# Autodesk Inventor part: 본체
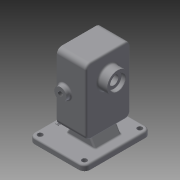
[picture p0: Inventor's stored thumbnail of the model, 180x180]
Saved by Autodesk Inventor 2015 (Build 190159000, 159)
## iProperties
Created: 2020-04
Part Number: 본체
Material: 일반
Document SubType Name: Modeling
Designer: CAD-08
Density: 1 g/cm^3
Appearance: 기본값
Author: CAD-08
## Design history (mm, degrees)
sketch "스케치1"
  geometry: L1 (50, -60)-(-50, -60); L2 (-50, -60)-(-50, 60); L3 (-50, 60)-(50, 60); L4 (50, 60)-(50, -60); L5 (50, -60)-(-50, 60); L6 (-50, -60)-(50, 60); 1 further point
  constraints: 12 end point, 2 midpoint, 2 parallel, 1 horizontal, 1 perpendicular
  dimensions: "d0" = 100 distance of L2.end L3.end; "d1" = 120 distance of L1.end L2.end
extrude "돌출1" new body sketch "스케치1" distance "d2" = 10; taper "d3" = 0 deg
fillet "모깎기1" dims "d4" = 10
sketch "스케치2"
  geometry: A1 r 10 centre (-40, 50) between (-40, 60) and (-50, 50) reference; A2 r 10 centre (-40, -50) between (-50, -50) and (-40, -60) reference; A3 r 10 centre (40, -50) between (40, -60) and (50, -50) reference; A4 r 10 centre (40, 50) between (50, 50) and (40, 60) reference; 1 further point
hole "구멍1" sketch "스케치2" at (-40, -50), (-40, 50), (40, -50), (40, 50) diameter "d5" = 9; stored, may be unused: countersink angle "d9" = 90 deg, drill point angle "d11" = 118 deg; dims "d6" = 6, "d7" = 4, "d8" = 2, "d10" = 8
sketch "스케치3"
  geometry: L1 (50, -50)-(50, 50) reference; L2 (-20, 24)-(33, 24); L3 (33, 24)-(33, -24); L4 (33, -24)-(-20, -24); L5 (-20, -24)-(-20, 24); L6 (0, 0)-(-20, 0)
  constraints: 10 end point, 2 horizontal, 2 parallel, 1 midpoint, 1 perpendicular, 1 other
  dimensions: "d12" = 48 distance of L4.end L2.start; "d13" = 53 distance of L3.end L4.end; "d14" = 17 distance between parallel lines of L1 L3
extrude "돌출2" join sketch "스케치3" distance "d15" = 50; taper "d16" = 0 deg
feature "면 기울기1" dims angle "d17" = 30 deg
feature "면 기울기2" dims angle "d18" = 30 deg
sketch "스케치5"
  geometry: L1 (-33, 10)-(-6.5, 55.899) reference; L2 (-6.5, 55.899)-(20, 10) reference; L3 (20, 10)-(50, 10) reference; L4 (50, 10)-(50, 0) reference; L5 (50, 0)-(-50, 0) reference; L6 (-50, 0)-(-50, 10) reference; L7 (-50, 10)-(-33, 10) reference; L8 (20, 30)-(-33, 30); L9 (-33, 30)-(-33, 150); L10 (-33, 150)-(20, 150); L11 (20, 150)-(20, 30); L12 (-6.5, 55.899)-(-6.5, 30); 1 further point
  constraints: 10 end point, 2 parallel, 1 horizontal, 1 midpoint, 1 perpendicular, 1 vertical, 1 other
  dimensions: "d26" = 120 distance of L10.end L8.start; "d27" = 53 distance of L9.end L10.end; "d28" = 150 distance between parallel lines of L5 L10
extrude "돌출4" join sketch "스케치5" stored distance "d29" = 80; taper "d30" = 0 deg
fillet "모깎기2" dims "d31" = 9
sketch "스케치7"
  geometry: A1 r 9 centre (9, 62) between (9, 71) and (0, 62) reference; A2 r 9 centre (9, 0) between (0, 0) and (9, -9) reference; A3 r 9 centre (111, 0) between (111, -9) and (120, 0) reference; A4 r 9 centre (111, 62) between (120, 62) and (111, 71) reference; 1 further point
hole "구멍2" sketch "스케치7" at (111, 62), (111, 0), (9, 62), (9, 0) diameter "d37" = 4.134; stored, may be unused: countersink angle "d41" = 90 deg, drill point angle "d43" = 118 deg; dims "d38" = 10, "d39" = 4, "d40" = 2, "d42" = 12
sketch "스케치8"
  geometry: C1 r 2.067 at (111, 62) reference; 2 further points
  constraints: 1 horizontal alignment
  dimensions: "d44" = 29 distance of C1.centre point (82, 62)
hole "구멍3" sketch "스케치8" at (82, 62) diameter "d45" = 4.134; stored, may be unused: countersink angle "d49" = 90 deg, drill point angle "d51" = 118 deg; dims "d46" = 10, "d47" = 4, "d48" = 2, "d50" = 12
sketch "스케치9"
  geometry: C1 r 2.067 at (9, 62) reference; 2 further points
  constraints: 1 horizontal alignment
  dimensions: "d52" = 29 distance of C1.centre point (38, 62)
hole "구멍4" sketch "스케치9" at (38, 62) diameter "d53" = 4.134; stored, may be unused: countersink angle "d57" = 90 deg, drill point angle "d59" = 118 deg; dims "d54" = 10, "d55" = 4, "d56" = 2, "d58" = 12
sketch "스케치12"
  geometry: L1 (9, 71)-(111, 71) reference; L2 (14, 31)-(106, 31); L3 (38, 7)-(82, 7); L4 (82, 55)-(38, 55); L5 (-30, -19)-(-30, 81) reference; A1 r 24 centre (38, 31) between (38, 55) and (38, 7); A2 r 24 centre (82, 31) between (82, 7) and (82, 55); 4 further points
  constraints: 8 end point, 6 point on circle, 4 tangent, 3 midpoint, 2 centre point, 2 point on line, 1 horizontal, 1 horizontal alignment, 1 parallel, 1 vertical alignment
  dimensions: "d71" = 24 radius of A2; "d72" = 92 distance of L2.start L2.end
extrude "돌출7" cut sketch "스케치12" distance "d73" = 29; taper "d74" = 0 deg
sketch "스케치13"
  geometry: L1 (-20, 141)-(-20, 39) reference; L2 (40, 0)-(-40, 0) reference; C1 r 11 at (-5.5, 90); 1 further point
  constraints: 1 centre point
  dimensions: "d75" = 22 diameter of C1; "d76" = 14.5 distance from line of L1 C1.centre; "d77" = 90 distance from line of L2 C1.centre
extrude "돌출8" join sketch "스케치13" distance "d78" = 8; taper "d79" = 0 deg
sketch "스케치14"
  geometry: C1 r 11 at (0, 0) reference; 1 further point
hole "구멍6" sketch "스케치14" at (0, 0) diameter "d80" = 8.376; stored, may be unused: countersink angle "d84" = 90 deg, drill point angle "d86" = 118 deg; dims "d81" = 20, "d82" = 4, "d83" = 2, "d85" = 27.3
sketch "스케치15"
  geometry: C1 r 12.5 at (82, 31); A1 r 24 centre (82, 31) between (82, 7) and (82, 55) reference; 1 further point
  constraints: 1 centre point, 1 coincident
  dimensions: "d87" = 25 diameter of C1
extrude "돌출9" cut sketch "스케치15" distance "d88" = 15; taper "d89" = 0 deg
sketch "스케치16"
  geometry: C1 r 12.5 at (38, 31); A1 r 24 centre (38, 31) between (38, 55) and (38, 7) reference; 1 further point
  constraints: 1 centre point, 1 coincident
  dimensions: "d90" = 25 diameter of C1
extrude "돌출10" cut sketch "스케치16" distance "d91" = 15; taper "d92" = 0 deg
sketch "스케치17"
  geometry: C1 r 12.5 at (0, 0) reference; C2 r 8.5 at (0, 0); 1 further point
  constraints: 1 centre point, 1 coincident
  dimensions: "d93" = 17 diameter of C2
extrude "돌출11" cut sketch "스케치17" stored distance "d94" = 15; taper "d95" = 0 deg
sketch "스케치18"
  geometry: C1 r 8.5 at (38, 31) reference; C2 r 19 at (38, 31); 1 further point
  constraints: 1 centre point, 1 coincident
  dimensions: "d96" = 38 diameter of C2
extrude "돌출12" join sketch "스케치18" distance "d97" = 17; taper "d98" = 0 deg
sketch "스케치19"
  geometry: C1 r 8.5 at (0, 0) reference; C2 r 19 at (0, 0) reference; C3 r 14 at (0, 0); 1 further point
  constraints: 1 centre point, 1 coincident
  dimensions: "d99" = 28 diameter of C3
extrude "돌출13" cut sketch "스케치19" distance "d100" = 7.3; taper "d101" = 0 deg
chamfer "모따기1" distance "d102" = 0.7; stored, may be unused: second distance "d103" = 2, angle "d104" = 30 deg
fillet "모깎기3" dims "d105" = 0.5
fillet "모깎기4" dims "d106" = 3
fillet "모깎기5" dims "d107" = 3
fillet "모깎기6" dims "d108" = 3
fillet "모깎기7" dims "d109" = 3
fillet "모깎기8" dims "d110" = 3
fillet "모깎기9" dims "d111" = 3
chamfer "모따기2" distance "d112" = 1; stored, may be unused: second distance "d113" = 2, angle "d114" = 30 deg
sketch "스케치20"
  geometry: L1 (40, 60)-(-40, 60) reference; L2 (-50, 50)-(-50, -50) reference; 2 further points
  constraints: 1 other
  dimensions: "d115" = 60 distance from line of point (-40, 0) L1; "d116" = 10 distance from line of L2 point (-40, 0)
feature "엠보싱1" sketch "스케치20" dims "d117" = 1, "d118" = 0
node "솔리드1"
mirror "대칭1"
mirror "대칭2"
mirror "대칭4"
node "절단 모서리 투영2"
